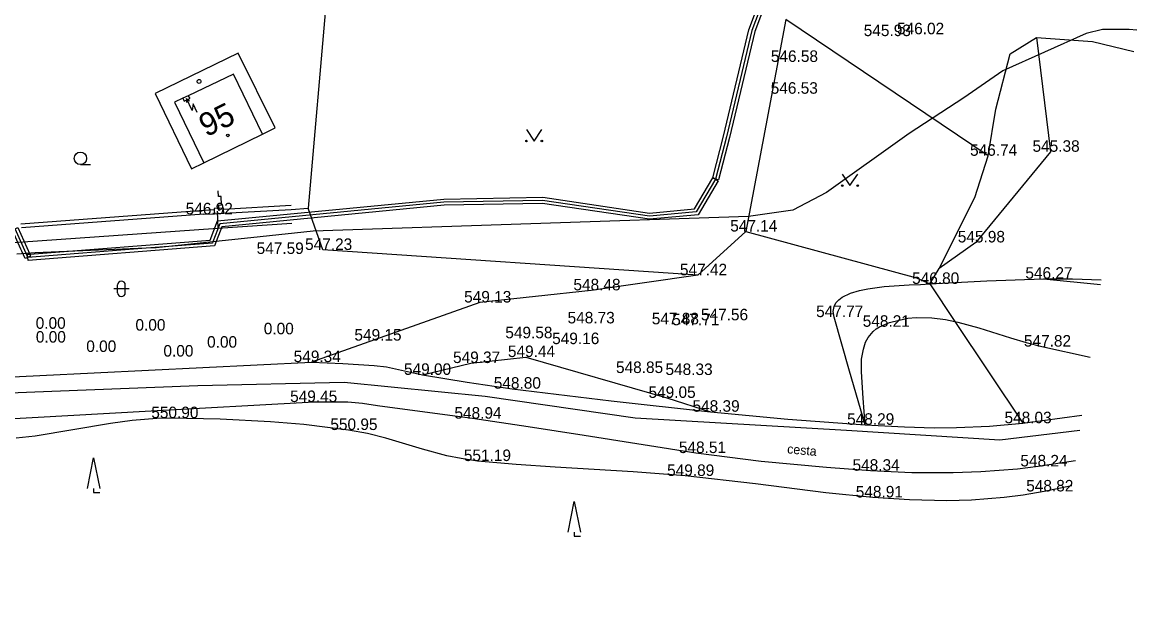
# Model space of a CAD drawing. Extents: x -669995 to -669686, y -1125551 to -1125263.
# Drawn here: x -669770.3 to -669697.7, y -1125420.8 to -1125382.3 of the extents above; entities that cross this region are included whole.
import ezdxf

# ---------------------------------------------------------------- set-up
doc = ezdxf.new("R2010")
doc.units = 0
for name, color, linetype in [('G_Bod_tecka', 7, 'Continuous'), ('G_Bod_vyska', 7, 'Continuous'), ('G_Breh_Teren', 7, 'Continuous'), ('G_Budovy-znacky', 7, 'Continuous'), ('G_Budovy_Objekty', 7, 'Continuous'), ('G_Cesty_Schody', 7, 'Continuous'), ('G_Cisla_orientacni', 7, 'Continuous'), ('G_Ploty', 7, 'Continuous'), ('G_Ploty_vstupy', 7, 'Continuous'), ('G_Popisy_povrchu', 7, 'Continuous'), ('G_Site-Rozvadece', 7, 'Continuous'), ('G_Z_CHRANICKA-TEPLOVOD_kotovane', 7, 'Continuous'), ('G_Z_ELsilove_podz_kotovane', 7, 'Continuous'), ('G_Z_ELsilove_zrusene', 7, 'Continuous'), ('G_Z_PLYNY_podz_geodeticky', 7, 'Continuous'), ('G_Zelen-okraj', 7, 'Continuous'), ('G_Zelen-Znacky', 7, 'Continuous')]:
    doc.layers.add(name, color=color, linetype=linetype)

msp = doc.modelspace()

# ---------------------------------------------------------------- linework, layer by layer
at = {"layer": 'G_Bod_tecka'}
for p, q in [((-669714.34, -1125383.24), (-669714.34, -1125383.24)), ((-669712.14, -1125383.12), (-669712.14, -1125383.12)), ((-669720.37, -1125384.92), (-669720.37, -1125384.92)), ((-669720.38, -1125386.99), (-669720.38, -1125386.99)), ((-669707.41, -1125391.03), (-669707.41, -1125391.03)), ((-669703.36, -1125390.77), (-669703.36, -1125390.77)), ((-669758.44, -1125394.84), (-669758.44, -1125394.84)), ((-669723.17, -1125395.96), (-669723.17, -1125395.96)), ((-669708.22, -1125396.67), (-669708.22, -1125396.67)), ((-669753.84, -1125397.42), (-669753.84, -1125397.42)), ((-669750.69, -1125397.16), (-669750.69, -1125397.16)), ((-669726.3, -1125398.81), (-669726.3, -1125398.81)), ((-669703.81, -1125399.03), (-669703.81, -1125399.03)), ((-669733.23, -1125399.79), (-669733.23, -1125399.79)), ((-669711.16, -1125399.37), (-669711.16, -1125399.37)), ((-669740.48, -1125400.58), (-669740.48, -1125400.58)), ((-669733.61, -1125401.94), (-669733.61, -1125401.94)), ((-669728.13, -1125402), (-669728.13, -1125402)), ((-669726.87, -1125402.06), (-669726.87, -1125402.06)), ((-669724.92, -1125401.74), (-669724.92, -1125401.74)), ((-669717.44, -1125401.53), (-669717.44, -1125401.53)), ((-669714.47, -1125402.16), (-669714.47, -1125402.16)), ((-669768.6, -1125402.29), (-669768.6, -1125402.29)), ((-669762.11, -1125402.41), (-669762.11, -1125402.41)), ((-669753.76, -1125402.65), (-669753.76, -1125402.65)), ((-669737.66, -1125402.91), (-669737.66, -1125402.91)), ((-669768.59, -1125403.19), (-669768.59, -1125403.19)), ((-669757.45, -1125403.52), (-669757.45, -1125403.52)), ((-669747.62, -1125403.06), (-669747.62, -1125403.06)), ((-669734.74, -1125403.29), (-669734.74, -1125403.29)), ((-669703.92, -1125403.45), (-669703.92, -1125403.45)), ((-669765.31, -1125403.8), (-669765.31, -1125403.8)), ((-669760.29, -1125404.1), (-669760.29, -1125404.1)), ((-669737.49, -1125404.13), (-669737.49, -1125404.13)), ((-669751.43, -1125404.46), (-669751.43, -1125404.46)), ((-669741.06, -1125404.52), (-669741.06, -1125404.52)), ((-669744.21, -1125405.29), (-669744.21, -1125405.29)), ((-669730.46, -1125405.17), (-669730.46, -1125405.17)), ((-669727.24, -1125405.3), (-669727.24, -1125405.3)), ((-669738.39, -1125406.19), (-669738.39, -1125406.19)), ((-669751.66, -1125407.06), (-669751.66, -1125407.06)), ((-669728.32, -1125406.79), (-669728.32, -1125406.79)), ((-669725.48, -1125407.69), (-669725.48, -1125407.69)), ((-669760.65, -1125408.11), (-669760.65, -1125408.11)), ((-669740.97, -1125408.14), (-669740.97, -1125408.14)), ((-669715.42, -1125408.54), (-669715.42, -1125408.54)), ((-669705.16, -1125408.44), (-669705.16, -1125408.44)), ((-669749.02, -1125408.88), (-669749.02, -1125408.88)), ((-669740.64, -1125410.9), (-669740.64, -1125410.9)), ((-669726.43, -1125410.38), (-669726.43, -1125410.38)), ((-669715.07, -1125411.53), (-669715.07, -1125411.53)), ((-669704.15, -1125411.25), (-669704.15, -1125411.25)), ((-669727.13, -1125411.87), (-669727.13, -1125411.87)), ((-669703.77, -1125412.88), (-669703.77, -1125412.88)), ((-669714.92, -1125413.27), (-669714.92, -1125413.27))]:
    msp.add_line(p, q, dxfattribs=at)
at = {"layer": 'G_Breh_Teren'}
for p, q in [((-669707.41, -1125391.03), (-669720.57, -1125382.16)), ((-669704.26, -1125383.34), (-669703.36, -1125390.77)), ((-669703.36, -1125390.77), (-669708.22, -1125396.67)), ((-669726.3, -1125398.81), (-669733.23, -1125399.79)), ((-669733.23, -1125399.79), (-669740.48, -1125400.58)), ((-669740.48, -1125400.58), (-669751.43, -1125404.46)), ((-669741.06, -1125404.52), (-669737.49, -1125404.13)), ((-669737.49, -1125404.13), (-669728.32, -1125406.79)), ((-669744.21, -1125405.29), (-669741.06, -1125404.52)), ((-669728.32, -1125406.79), (-669725.48, -1125407.69))]:
    msp.add_line(p, q, dxfattribs=at)
for points in [[(-669708.22, -1125396.67), (-669710.6, -1125398.37)], [(-669711.21, -1125399.37), (-669707.49, -1125399.16), (-669703.81, -1125399.03), (-669701.92, -1125399.03), (-669700.056, -1125399.098)], [(-669703.81, -1125399.03), (-669700.101, -1125399.416)], [(-669715.42, -1125408.54), (-669716.43, -1125405.04), (-669717.44, -1125401.53), (-669717.5, -1125401.16), (-669717.44, -1125400.85), (-669717.31, -1125400.6), (-669717.13, -1125400.4), (-669716.9, -1125400.23), (-669716.36, -1125399.97), (-669715.79, -1125399.8), (-669715.24, -1125399.68), (-669714.18, -1125399.54), (-669712.56, -1125399.44), (-669711.82, -1125399.4), (-669711.21, -1125399.37)], [(-669715.42, -1125408.54), (-669715.54, -1125406.81), (-669715.65, -1125405.09), (-669715.64, -1125404.26), (-669715.53, -1125403.62), (-669715.38, -1125403.17), (-669715.22, -1125402.86), (-669714.9, -1125402.46), (-669714.7, -1125402.29), (-669714.47, -1125402.16), (-669713.82, -1125401.89), (-669713.21, -1125401.72), (-669712.64, -1125401.61), (-669712.09, -1125401.56), (-669711.07, -1125401.58), (-669710.18, -1125401.69), (-669709.58, -1125401.81)], [(-669709.58, -1125401.81), (-669709.39, -1125401.85), (-669708.01, -1125402.23), (-669705.95, -1125402.89), (-669704.93, -1125403.19), (-669703.92, -1125403.45), (-669700.774, -1125404.137)], [(-669701.966, -1125412.514), (-669703.77, -1125412.88), (-669705.14, -1125413.12), (-669706.36, -1125413.28), (-669708.49, -1125413.44), (-669710.1, -1125413.48), (-669712.52, -1125413.43), (-669714.92, -1125413.27), (-669717.97, -1125412.96), (-669722.55, -1125412.39), (-669727.13, -1125411.87), (-669730.5, -1125411.61), (-669735.58, -1125411.3), (-669738.11, -1125411.13), (-669740.64, -1125410.9), (-669741.7, -1125410.74), (-669742.62, -1125410.55), (-669744.21, -1125410.12), (-669746.6, -1125409.42), (-669747.8, -1125409.11), (-669749.02, -1125408.88), (-669751.93, -1125408.52), (-669754.11, -1125408.34), (-669757.38, -1125408.17), (-669760.65, -1125408.11), (-669761.5, -1125408.13), (-669763.11, -1125408.26), (-669764.51, -1125408.46), (-669769.42, -1125409.28), (-669770.65, -1125409.41)]]:
    msp.add_lwpolyline(points, dxfattribs=at)
at = {"layer": 'G_Budovy-znacky'}
for centre, radius in [((-669758.75, -1125386.19), 0.125), ((-669756.88, -1125389.7), 0.0875)]:
    msp.add_circle(centre, radius, dxfattribs=at)
at = {"layer": 'G_Budovy_Objekty'}
for p, q in [((-669756.2, -1125384.35), (-669761.61, -1125386.98)), ((-669753.81, -1125389.22), (-669756.2, -1125384.35)), ((-669756.52, -1125385.72), (-669759.45, -1125387.12)), ((-669754.62, -1125389.62), (-669756.52, -1125385.72)), ((-669761.61, -1125386.98), (-669759.25, -1125391.87)), ((-669759.81, -1125387.29), (-669760.35, -1125387.55)), ((-669760.35, -1125387.55), (-669758.44, -1125391.48)), ((-669759.45, -1125387.12), (-669759.81, -1125387.29)), ((-669758.44, -1125391.48), (-669754.62, -1125389.62)), ((-669754.62, -1125389.62), (-669753.81, -1125389.22)), ((-669759.25, -1125391.87), (-669758.44, -1125391.48))]:
    msp.add_line(p, q, dxfattribs=at)
at = {"layer": 'G_Cesty_Schody'}
for points in [[(-669831.37, -1125419.84), (-669824.18, -1125415.63), (-669816.98, -1125411.41), (-669814.49, -1125410.06), (-669810.62, -1125408.26), (-669806.64, -1125406.64), (-669804.01, -1125405.78), (-669801.31, -1125405.22), (-669798.68, -1125404.88), (-669794.74, -1125404.59), (-669790.8, -1125404.52), (-669786.26, -1125404.75), (-669779.47, -1125405.34), (-669776.07, -1125405.53), (-669772.67, -1125405.5), (-669762.05, -1125404.98), (-669751.43, -1125404.46)], [(-669751.43, -1125404.46), (-669749.39, -1125404.56), (-669747.36, -1125404.67), (-669746.56, -1125404.76), (-669745.39, -1125405.03), (-669744.21, -1125405.29), (-669741.3, -1125405.76), (-669738.39, -1125406.19), (-669731.94, -1125406.98), (-669725.48, -1125407.69), (-669720.45, -1125408.17), (-669715.42, -1125408.54), (-669712.86, -1125408.68), (-669710.93, -1125408.73), (-669709.48, -1125408.72), (-669707.32, -1125408.64), (-669705.16, -1125408.44), (-669701.313, -1125407.923)], [(-669827.31, -1125430.89), (-669827.81, -1125427.44), (-669828.32, -1125424), (-669828.27, -1125423.02), (-669828.02, -1125422.32), (-669827.38, -1125421.32), (-669826.53, -1125420.43), (-669825.24, -1125419.34), (-669822.95, -1125417.69), (-669821.19, -1125416.63), (-669818.5, -1125415.21), (-669815.71, -1125413.85), (-669812.14, -1125411.91), (-669809.03, -1125410.3), (-669806.44, -1125409.64), (-669803.17, -1125408.56), (-669800.72, -1125407.98), (-669797.03, -1125407.45), (-669793.32, -1125407.28), (-669785.67, -1125407.31), (-669776.28, -1125408.27), (-669772.35, -1125408.22), (-669761.86, -1125407.64), (-669751.66, -1125407.06)], [(-669701.735, -1125410.89), (-669704.15, -1125411.25), (-669705.51, -1125411.42), (-669707.89, -1125411.61), (-669709.69, -1125411.67), (-669712.38, -1125411.66), (-669715.07, -1125411.53), (-669717.92, -1125411.33), (-669722.18, -1125410.92), (-669726.43, -1125410.38), (-669733.7, -1125409.24), (-669737.33, -1125408.67), (-669740.97, -1125408.14), (-669744.06, -1125407.72), (-669747.15, -1125407.31), (-669748.12, -1125407.15), (-669749.08, -1125407.06), (-669750.37, -1125407.06), (-669751.66, -1125407.06)]]:
    msp.add_lwpolyline(points, dxfattribs=at)
at = {"layer": 'G_Ploty'}
for p, q in [((-669750.09, -1125376.5), (-669751.65, -1125394.45)), ((-669720.57, -1125382.16), (-669723.17, -1125395.96)), ((-669758.46, -1125394.59), (-669770.35, -1125395.48)), ((-669758.44, -1125394.84), (-669770.31, -1125395.73)), ((-669757.76, -1125394.55), (-669758.46, -1125394.59)), ((-669758.44, -1125394.84), (-669757.74, -1125394.8)), ((-669752.76, -1125394.26), (-669757.16, -1125394.52)), ((-669757.14, -1125394.77), (-669752.75, -1125394.52)), ((-669750.69, -1125397.16), (-669751.65, -1125394.45)), ((-669726.3, -1125398.81), (-669750.69, -1125397.16))]:
    msp.add_line(p, q, dxfattribs=at)
at = {"layer": 'G_Ploty_vstupy'}
for p, q in [((-669752.75, -1125394.52), (-669751.65, -1125394.45)), ((-669726.3, -1125398.81), (-669723.17, -1125395.96))]:
    msp.add_line(p, q, dxfattribs=at)
at = {"layer": 'G_Site-Rozvadece'}
for p, q in [((-669759.81, -1125387.29), (-669759.72, -1125387.47)), ((-669759.72, -1125387.47), (-669759.36, -1125387.3)), ((-669759.203, -1125388.09), (-669759.579, -1125387.3)), ((-669759.375, -1125387.474), (-669759.579, -1125387.3)), ((-669759.579, -1125387.3), (-669759.573, -1125387.568)), ((-669759.45, -1125387.12), (-669759.36, -1125387.3)), ((-669759.139, -1125387.644), (-669759.203, -1125388.09)), ((-669758.869, -1125388.209), (-669759.139, -1125387.644))]:
    msp.add_line(p, q, dxfattribs=at)
msp.add_lwpolyline([(-669757.45, -1125394.61), (-669757.468, -1125394.242), (-669757.285, -1125394.233), (-669757.313, -1125393.682), (-669757.495, -1125393.69), (-669757.515, -1125393.322)], dxfattribs=at)
msp.add_lwpolyline([(-669757.76, -1125394.46), (-669757.76, -1125394.55), (-669757.74, -1125394.8), (-669757.14, -1125394.77), (-669757.16, -1125394.52), (-669757.16, -1125394.43)], close=True, dxfattribs=at)
at = {"layer": 'G_Z_CHRANICKA-TEPLOVOD_kotovane'}
for points in [[(-669725.327, -1125392.473), (-669724.624, -1125389.742), (-669722.972, -1125382.821), (-669720.904, -1125377.309), (-669720.146, -1125372.532), (-669718.876, -1125366.96), (-669717.277, -1125358.154), (-669717.078, -1125358.19), (-669716.883, -1125358.226), (-669716.883, -1125358.227), (-669718.484, -1125367.04), (-669719.754, -1125372.608), (-669720.516, -1125377.411), (-669722.588, -1125382.939), (-669724.236, -1125389.838), (-669724.946, -1125392.6), (-669725.14, -1125392.55), (-669725.334, -1125392.5)], [(-669725.327, -1125392.473), (-669725.312, -1125392.448), (-669725.14, -1125392.55), (-669724.968, -1125392.652), (-669726.28, -1125394.87), (-669729.446, -1125395.161), (-669736.413, -1125394.13), (-669742.808, -1125394.25), (-669757.267, -1125395.647), (-669757.738, -1125396.9), (-669769.875, -1125397.839), (-669769.89, -1125397.64), (-669769.905, -1125397.441), (-669769.765, -1125397.43), (-669758.022, -1125396.52), (-669757.553, -1125395.273), (-669742.831, -1125393.85), (-669736.387, -1125393.73), (-669729.434, -1125394.759), (-669726.52, -1125394.49)], [(-669770.538, -1125395.708), (-669769.765, -1125397.43), (-669769.708, -1125397.558), (-669769.89, -1125397.64), (-669770.073, -1125397.722), (-669770.29, -1125397.238), (-669770.305, -1125397.203), (-669770.349, -1125397.105), (-669770.79, -1125396.122), (-669770.903, -1125395.872)]]:
    msp.add_lwpolyline(points, close=True, dxfattribs=at)
at = {"layer": 'G_Z_ELsilove_podz_kotovane'}
for points in [[(-669720.71, -1125377.36), (-669722.78, -1125382.88), (-669724.43, -1125389.79), (-669725.14, -1125392.55), (-669726.4, -1125394.68), (-669729.44, -1125394.96), (-669736.4, -1125393.93), (-669742.82, -1125394.05), (-669757.41, -1125395.46), (-669757.848, -1125396.626), (-669757.88, -1125396.71), (-669760.726, -1125396.93), (-669762.193, -1125397.044), (-669769.89, -1125397.64), (-669770.005, -1125397.384), (-669770.72, -1125395.79)], [(-669825.82, -1125421.69), (-669825.4, -1125420.37), (-669823.47, -1125418.72), (-669817.66, -1125414.93), (-669810.41, -1125410.58), (-669804, -1125408.54), (-669793.75, -1125407.46), (-669779.34, -1125406.79), (-669768.33, -1125406.35), (-669758.83, -1125405.98), (-669749.3, -1125405.76), (-669740.13, -1125406.68), (-669730.37, -1125408.08), (-669716.63, -1125408.89), (-669706.64, -1125409.51), (-669701.451, -1125408.897)]]:
    msp.add_lwpolyline(points, dxfattribs=at)
at = {"layer": 'G_Z_ELsilove_zrusene'}
msp.add_lwpolyline([(-669697.745, -1125382.863), (-669698.231, -1125382.803), (-669699.96, -1125382.805), (-669701.025, -1125383.06), (-669706.449, -1125385.502), (-669708.984, -1125387.261), (-669712.54, -1125389.586), (-669717.937, -1125393.416), (-669720.12, -1125394.561), (-669723.008, -1125394.973), (-669751.334, -1125395.941), (-669754.772, -1125396.301), (-669757.848, -1125396.626), (-669760.726, -1125396.93), (-669761.545, -1125397.017), (-669762.193, -1125397.044), (-669769.416, -1125397.345), (-669770.005, -1125397.384), (-669770.599, -1125397.423)], dxfattribs=at)
msp.add_lwpolyline([(-669697.745, -1125382.863), (-669698.231, -1125382.803), (-669699.96, -1125382.805), (-669701.025, -1125383.06), (-669706.449, -1125385.502), (-669708.984, -1125387.261), (-669712.54, -1125389.586), (-669717.937, -1125393.416), (-669720.12, -1125394.561), (-669723.008, -1125394.973), (-669751.334, -1125395.941), (-669754.772, -1125396.301), (-669757.848, -1125396.626), (-669760.726, -1125396.93), (-669761.545, -1125397.017), (-669762.193, -1125397.044), (-669769.416, -1125397.345), (-669770.005, -1125397.384), (-669770.599, -1125397.423)], dxfattribs=at)
at = {"layer": 'G_Z_PLYNY_podz_geodeticky'}
for points in [[(-669757.58, -1125394.63), (-669757.52, -1125395.74)], [(-669839.96, -1125401.69), (-669839.65, -1125401.68), (-669829.38, -1125401.08), (-669823.72, -1125400.23), (-669823.35, -1125400.2), (-669822.91, -1125400.13), (-669812.4, -1125399.44), (-669811.498, -1125399.357), (-669810.66, -1125399.28), (-669809.29, -1125399.19), (-669796.31, -1125398.41), (-669789.98, -1125398.03), (-669757.52, -1125395.74), (-669752.71, -1125395.41)]]:
    msp.add_lwpolyline(points, dxfattribs=at)
at = {"layer": 'G_Zelen-okraj'}
for p, q in [((-669705.97, -1125384.39), (-669704.26, -1125383.34)), ((-669704.26, -1125383.34), (-669700.63, -1125383.6)), ((-669700.63, -1125383.6), (-669697.942, -1125384.246)), ((-669706.92, -1125388), (-669705.97, -1125384.39)), ((-669707.41, -1125391.03), (-669706.92, -1125388)), ((-669708.28, -1125393.74), (-669707.41, -1125391.03)), ((-669723.17, -1125395.96), (-669712.07, -1125398.98))]:
    msp.add_line(p, q, dxfattribs=at)
for points in [[(-669710.6, -1125398.37), (-669708.28, -1125393.74)], [(-669711.21, -1125399.37), (-669710.6, -1125398.37)], [(-669712.07, -1125398.98), (-669711.21, -1125399.37)], [(-669711.21, -1125399.37), (-669709.58, -1125401.81)], [(-669709.58, -1125401.81), (-669705.16, -1125408.44)]]:
    msp.add_lwpolyline(points, dxfattribs=at)
at = {"layer": 'G_Zelen-Znacky'}
for p, q in [((-669737.45, -1125389.32), (-669736.95, -1125390.07)), ((-669736.95, -1125390.07), (-669736.45, -1125389.32)), ((-669766.472, -1125391.6), (-669765.822, -1125391.597)), ((-669716.9, -1125392.22), (-669716.4, -1125392.97)), ((-669716.4, -1125392.97), (-669715.9, -1125392.22)), ((-669763.3, -1125399.69), (-669764.3, -1125399.69)), ((-669764.05, -1125399.94), (-669764.05, -1125399.44)), ((-669763.55, -1125399.94), (-669763.55, -1125399.44)), ((-669766.01, -1125412.69), (-669765.61, -1125410.69)), ((-669765.61, -1125410.69), (-669765.21, -1125412.69)), ((-669765.61, -1125412.69), (-669765.61, -1125412.94)), ((-669765.61, -1125412.94), (-669765.21, -1125412.94)), ((-669734.74, -1125415.54), (-669734.34, -1125413.54)), ((-669734.34, -1125413.54), (-669733.94, -1125415.54)), ((-669734.34, -1125415.54), (-669734.34, -1125415.79)), ((-669734.34, -1125415.79), (-669733.94, -1125415.79))]:
    msp.add_line(p, q, dxfattribs=at)
for centre, radius in [((-669737.45, -1125390.07), 0.05), ((-669736.45, -1125390.07), 0.05), ((-669766.472, -1125391.197), 0.403), ((-669716.9, -1125392.97), 0.05), ((-669715.9, -1125392.97), 0.05)]:
    msp.add_circle(centre, radius, dxfattribs=at)
for centre, start, end in [((-669763.8, -1125399.44), 0, 180), ((-669763.8, -1125399.94), 180, 0)]:
    msp.add_arc(centre, 0.25, start, end, dxfattribs=at)

# ---------------------------------------------------------------- texts
at = {"layer": 'G_Bod_vyska'}
for s, p in [('545.93', (-669715.506, -1125383.24)), ('546.02', (-669713.339, -1125383.12)), ('546.58', (-669721.548, -1125384.92)), ('546.53', (-669721.558, -1125386.99)), ('546.74', (-669708.588, -1125391.03)), ('545.38', (-669704.524, -1125390.77)), ('546.92', (-669759.62, -1125394.84)), ('547.14', (-669724.192, -1125395.96)), ('547.23', (-669751.854, -1125397.16)), ('545.98', (-669709.386, -1125396.67)), ('547.59', (-669755.006, -1125397.42)), ('547.42', (-669727.464, -1125398.81)), ('546.27', (-669704.988, -1125399.03)), ('548.48', (-669734.394, -1125399.79)), ('546.80', (-669712.359, -1125399.37)), ('549.13', (-669741.504, -1125400.58)), ('547.77', (-669718.604, -1125401.53)), ('548.73', (-669734.774, -1125401.94)), ('547.88', (-669729.294, -1125402)), ('547.71', (-669727.972, -1125402.06)), ('547.56', (-669726.098, -1125401.74)), ('548.21', (-669715.572, -1125402.16)), ('0.00', (-669769.38, -1125402.29)), ('0.00', (-669762.89, -1125402.41)), ('0.00', (-669754.54, -1125402.65)), ('549.58', (-669738.826, -1125402.91)), ('0.00', (-669769.37, -1125403.19)), ('0.00', (-669758.23, -1125403.52)), ('549.15', (-669748.644, -1125403.06)), ('549.16', (-669735.778, -1125403.29)), ('547.82', (-669705.084, -1125403.45)), ('0.00', (-669766.09, -1125403.8)), ('0.00', (-669761.07, -1125404.1)), ('549.44', (-669738.656, -1125404.13)), ('549.34', (-669752.596, -1125404.46)), ('549.37', (-669742.226, -1125404.52)), ('548.85', (-669731.624, -1125405.17)), ('549.00', (-669745.419, -1125405.29)), ('548.33', (-669728.404, -1125405.3)), ('548.80', (-669739.576, -1125406.19)), ('549.45', (-669752.826, -1125407.06)), ('549.05', (-669729.508, -1125406.79)), ('548.39', (-669726.646, -1125407.69)), ('550.90', (-669761.859, -1125408.11)), ('548.94', (-669742.136, -1125408.14)), ('548.29', (-669716.586, -1125408.54)), ('548.03', (-669706.346, -1125408.44)), ('550.95', (-669750.208, -1125408.88)), ('551.19', (-669741.523, -1125410.9)), ('548.51', (-669727.532, -1125410.38)), ('548.34', (-669716.234, -1125411.53)), ('548.24', (-669705.314, -1125411.25)), ('549.89', (-669728.298, -1125411.87)), ('548.82', (-669704.934, -1125412.88)), ('548.91', (-669716.024, -1125413.27))]:
    msp.add_text(s, height=0.75, dxfattribs=at).set_placement(p)
at = {"layer": 'G_Cisla_orientacni'}
msp.add_text('95', height=1.5, rotation=25.93804, dxfattribs=at).set_placement((-669758.286, -1125389.831))
at = {"layer": 'G_Popisy_povrchu'}
msp.add_text('cesta', height=0.6, rotation=354.891, dxfattribs=at).set_placement((-669720.505, -1125410.398))

doc.saveas('drawing.dxf')
